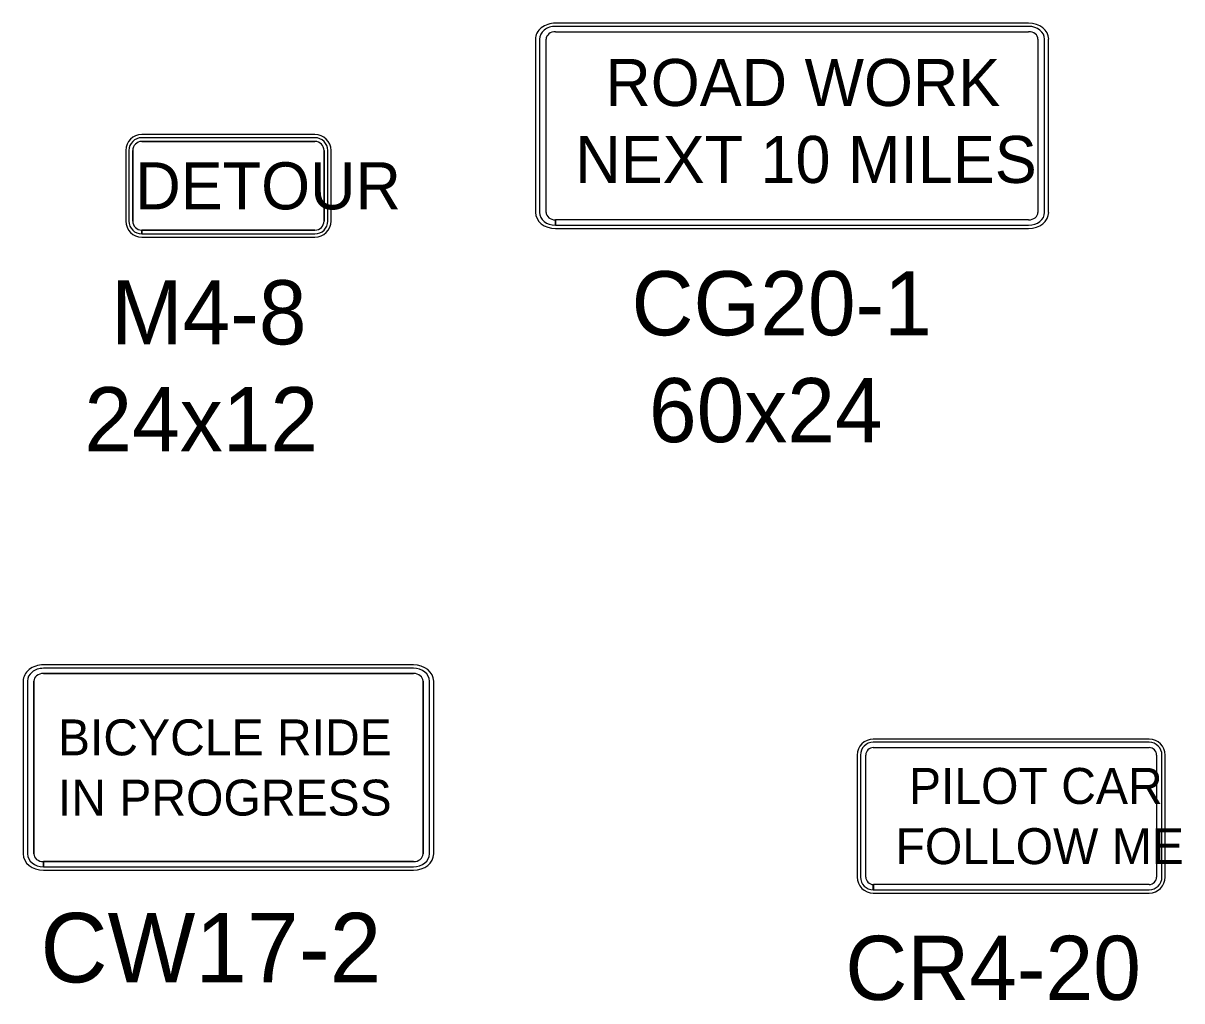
# Model space of a CAD drawing. Extents: x 1458 to 4498, y 17709 to 24109.
# Drawn here: x 1685.4 to 1956.2, y 21193.7 to 21422.3 of the extents above; entities that cross this region are included whole.
import ezdxf

# ---------------------------------------------------------------- set-up
doc = ezdxf.new("R2010")
doc.units = 0
doc.layers.add('P_TRAF_TCP_General', color=7, linetype='Continuous')

msp = doc.modelspace()

# ---------------------------------------------------------------- linework, layer by layer
at = {"layer": 'P_TRAF_TCP_General'}
for p, q in [((1920.39, 21422.3), (1809.81, 21422.3)), ((1920.39, 21421.55), (1809.81, 21421.55)), ((1809.81, 21420.31), (1920.39, 21420.31)), ((1805.12, 21418.56), (1805.12, 21378.07)), ((1806.06, 21418.56), (1806.06, 21378.07)), ((1807.62, 21378.07), (1807.62, 21418.56)), ((1922.57, 21418.56), (1922.57, 21378.07)), ((1924.14, 21378.07), (1924.14, 21418.56)), ((1925.07, 21378.07), (1925.07, 21418.56)), ((1753.59, 21396.28), (1713.11, 21396.28)), ((1753.59, 21395.53), (1713.11, 21395.53)), ((1753.59, 21395.53), (1713.11, 21395.53)), ((1753.59, 21394.65), (1713.11, 21394.65)), ((1713.11, 21394.65), (1753.59, 21394.65)), ((1709.36, 21392.53), (1709.36, 21376.04)), ((1710.11, 21392.53), (1710.11, 21376.04)), ((1710.11, 21392.53), (1710.11, 21376.04)), ((1710.98, 21392.53), (1710.98, 21376.04)), ((1710.98, 21376.04), (1710.98, 21392.53)), ((1755.71, 21376.04), (1755.71, 21392.53)), ((1755.71, 21392.53), (1755.71, 21376.04)), ((1756.59, 21376.04), (1756.59, 21392.53)), ((1756.59, 21376.04), (1756.59, 21392.53)), ((1757.34, 21376.04), (1757.34, 21392.53)), ((1809.81, 21375.07), (1809.81, 21376.32)), ((1920.39, 21376.32), (1809.82, 21376.32)), ((1809.82, 21376.32), (1809.82, 21375.07)), ((1713.11, 21373.91), (1753.59, 21373.91)), ((1713.11, 21373.04), (1713.11, 21373.91)), ((1713.11, 21373.04), (1753.59, 21373.04)), ((1753.59, 21373.91), (1713.12, 21373.91)), ((1713.12, 21373.91), (1713.12, 21373.04)), ((1713.12, 21373.04), (1753.59, 21373.04)), ((1809.81, 21374.32), (1920.39, 21374.32)), ((1809.82, 21375.07), (1920.39, 21375.07)), ((1713.11, 21372.29), (1753.59, 21372.29)), ((1776.6, 21272.28), (1690.13, 21272.28)), ((1776.6, 21271.48), (1690.13, 21271.48)), ((1776.6, 21270.28), (1690.13, 21270.28)), ((1690.13, 21270.28), (1776.6, 21270.28)), ((1685.39, 21268.48), (1685.39, 21228.09)), ((1686.38, 21268.48), (1686.38, 21228.09)), ((1687.88, 21268.48), (1687.88, 21228.09)), ((1687.88, 21228.09), (1687.88, 21268.48)), ((1778.85, 21228.09), (1778.85, 21268.48)), ((1778.85, 21268.48), (1778.85, 21228.09)), ((1780.35, 21228.09), (1780.35, 21268.48)), ((1781.35, 21228.09), (1781.35, 21268.48)), ((1948.56, 21254.93), (1884.08, 21254.93)), ((1948.56, 21254.18), (1884.08, 21254.18)), ((1880.34, 21251.18), (1880.34, 21222.69)), ((1881.09, 21251.18), (1881.09, 21222.69)), ((1882.34, 21222.69), (1882.34, 21251.18)), ((1884.08, 21252.93), (1948.56, 21252.93)), ((1950.31, 21251.18), (1950.31, 21222.69)), ((1951.56, 21222.69), (1951.56, 21251.18)), ((1952.31, 21222.69), (1952.31, 21251.18)), ((1690.13, 21226.29), (1776.6, 21226.29)), ((1690.13, 21225.1), (1690.13, 21226.29)), ((1690.13, 21224.3), (1776.6, 21224.3)), ((1776.6, 21226.29), (1690.15, 21226.29)), ((1690.15, 21226.29), (1690.15, 21225.1)), ((1690.15, 21225.1), (1776.6, 21225.1)), ((1884.08, 21219.7), (1884.08, 21220.94)), ((1884.09, 21218.95), (1948.56, 21218.95)), ((1948.56, 21220.94), (1884.1, 21220.94)), ((1884.1, 21220.94), (1884.1, 21219.7)), ((1884.1, 21219.7), (1948.56, 21219.7))]:
    msp.add_line(p, q, dxfattribs=at)
for centre, radius, start, end in [((1713.11, 21392.53), 3.75, 90, 180), ((1713.11, 21392.53), 3, 90, 180), ((1713.11, 21392.53), 3, 90, 180), ((1713.11, 21392.53), 2.12, 90, 180), ((1713.11, 21392.53), 2.12, 90, 180), ((1753.59, 21392.53), 3.75, 0, 90), ((1753.59, 21392.53), 3, 0, 90), ((1753.59, 21392.53), 3, 0, 90), ((1753.59, 21392.53), 2.12, 0, 90), ((1753.59, 21392.53), 2.12, 0, 90), ((1713.11, 21376.04), 3.75, 180, 270), ((1713.11, 21376.04), 3, 180, 270), ((1713.11, 21376.04), 3, 180, 270), ((1713.11, 21376.04), 2.12, 180, 270), ((1713.11, 21376.04), 2.12, 180, 270), ((1753.59, 21376.04), 3, 270, 0), ((1753.59, 21376.04), 2.12, 270, 0), ((1753.59, 21376.04), 3, 270, 0), ((1753.59, 21376.04), 2.12, 270, 0), ((1753.59, 21376.04), 3.75, 270, 0), ((1884.08, 21251.18), 3.75, 90, 180), ((1884.08, 21251.18), 3, 90, 180), ((1948.56, 21251.18), 3.75, 0, 90), ((1948.56, 21251.18), 3, 0, 90), ((1884.08, 21251.18), 1.75, 90, 180), ((1948.56, 21251.18), 1.75, 0, 90), ((1884.08, 21222.69), 3.75, 180, 270), ((1884.08, 21222.69), 3, 180, 270), ((1884.08, 21222.69), 1.75, 180, 270), ((1948.56, 21222.69), 3, 270, 0), ((1948.56, 21222.69), 1.75, 270, 0), ((1948.56, 21222.69), 3.75, 270, 0)]:
    msp.add_arc(centre, radius, start, end, dxfattribs=at)
for centre, major_axis, start_param, end_param in [((1809.81, 21418.56), (4.69, 0), 1.570796, 3.141593), ((1920.39, 21418.56), (4.69, 0), 0, 1.570796), ((1809.81, 21418.56), (3.75, 0), 1.570796, 3.141593), ((1809.81, 21418.56), (2.19, 0), 1.570796, 3.141593), ((1920.39, 21418.56), (3.75, 0), 0, 1.570796), ((1920.39, 21418.56), (2.19, 0), 0, 1.570796), ((1809.81, 21378.07), (4.69, 0), 3.141593, 4.712389), ((1809.81, 21378.07), (3.75, 0), 3.141593, 4.712389), ((1809.81, 21378.07), (2.19, 0), 3.141593, 4.712389), ((1920.39, 21378.07), (3.75, 0), 4.712389, 6.283185), ((1920.39, 21378.07), (2.19, 0), 4.712389, 6.283185), ((1920.39, 21378.07), (4.69, 0), 4.712389, 6.283185), ((1690.13, 21268.48), (4.75, 0), 1.570796, 3.141593), ((1690.13, 21268.48), (3.75, 0), 1.570796, 3.141593), ((1690.13, 21268.48), (2.25, 0), 1.570796, 3.141593), ((1690.13, 21268.48), (2.25, 0), 1.570796, 3.141593), ((1776.6, 21268.48), (4.75, 0), 0, 1.570796), ((1776.6, 21268.48), (3.75, 0), 0, 1.570796), ((1776.6, 21268.48), (2.25, 0), 0, 1.570796), ((1776.6, 21268.48), (2.25, 0), 0, 1.570796), ((1690.13, 21228.09), (4.75, 0), 3.141593, 4.712389), ((1690.13, 21228.09), (3.75, 0), 3.141593, 4.712389), ((1690.13, 21228.09), (2.25, 0), 3.141593, 4.712389), ((1690.13, 21228.09), (2.25, 0), 3.141593, 4.712389), ((1776.6, 21228.09), (2.25, 0), 4.712389, 6.283185), ((1776.6, 21228.09), (3.75, 0), 4.712389, 6.283185), ((1776.6, 21228.09), (2.25, 0), 4.712389, 6.283185), ((1776.6, 21228.09), (4.75, 0), 4.712389, 6.283185)]:
    msp.add_ellipse(centre, major_axis=major_axis, ratio=0.8, start_param=start_param, end_param=end_param, dxfattribs=at)

# ---------------------------------------------------------------- texts
for s, height, p in [('ROAD WORK', 10.996, (1821.46, 21402.94)), ('NEXT 10 MILES', 10.9956, (1814.43, 21384.95)), ('DETOUR', 10.996, (1711.6, 21378.78)), ('M4-8', 14.994, (1705.94, 21347.21)), ('CG20-1', 14.994, (1827.58, 21349.33)), ('60x24', 14.994, (1831.65, 21324.34)), ('24x12', 14.994, (1699.7, 21322.22)), ('BICYCLE RIDE', 8.4, (1693.51, 21251.13)), ('PILOT CAR', 8.4, (1892.43, 21239.78)), ('IN PROGRESS', 8.4, (1693.5, 21237.05)), ('FOLLOW ME', 8.4, (1889.28, 21225.7)), ('CW17-2', 16.25, (1689.42, 21198.05)), ('CR4-20', 14.994, (1877.55, 21193.96))]:
    msp.add_text(s, height=height, dxfattribs=at).set_placement(p)

doc.saveas('drawing.dxf')
